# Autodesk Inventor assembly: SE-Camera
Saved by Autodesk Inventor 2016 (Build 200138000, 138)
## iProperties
Created: 2013-08
Part Number: SE-Camera
Document SubType Name: Assembly
Designer: hilarion
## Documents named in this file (8)
- S:\TSTI2D\Documents en consultation\etude de cas 1  webcam\Webcam motorisee\SE-Camera.iam
- S:\TSTI2D\Documents en consultation\etude de cas 1  webcam\Webcam motorisee\Demi-boitier avant.ipt
- S:\TSTI2D\Documents en consultation\etude de cas 1  webcam\Webcam motorisee\Demi-boitier arriere.ipt
- S:\TSTI2D\Documents en consultation\etude de cas 1  webcam\Webcam motorisee\Collerette.ipt
- S:\TSTI2D\Documents en consultation\etude de cas 1  webcam\Webcam motorisee\Mini camera.ipt
- S:\TSTI2D\Documents en consultation\etude de cas 1  webcam\Webcam motorisee\Carte electronique.ipt
- S:\TSTI2D\Documents en consultation\etude de cas 1  webcam\Webcam motorisee\Moto-reducteur horizontal.ipt
- S:\TSTI2D\Documents en consultation\etude de cas 1  webcam\Webcam motorisee\VisCBCrucFendueF1.ipt
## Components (10 placed, 7 different names)
1. Demi-boitier avant:1
2. Demi-boitier arriere:1
3. Collerette:1
4. Mini camera:1
5. Carte electronique:1
6. Moto-reducteur horizontal:1
7. VisCBCrucFendueF1:1
8. VisCBCrucFendueF1:2
9. VisCBCrucFendueF1:3
10. VisCBCrucFendueF1:4
